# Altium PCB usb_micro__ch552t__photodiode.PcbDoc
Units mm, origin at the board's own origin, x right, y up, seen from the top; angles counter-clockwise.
Board outline 56 x 30 mm, 2 copper layers (Top, Bottom), stack 0 mm thick; 22 components, 15 nets, 85 pads, 32 vias.
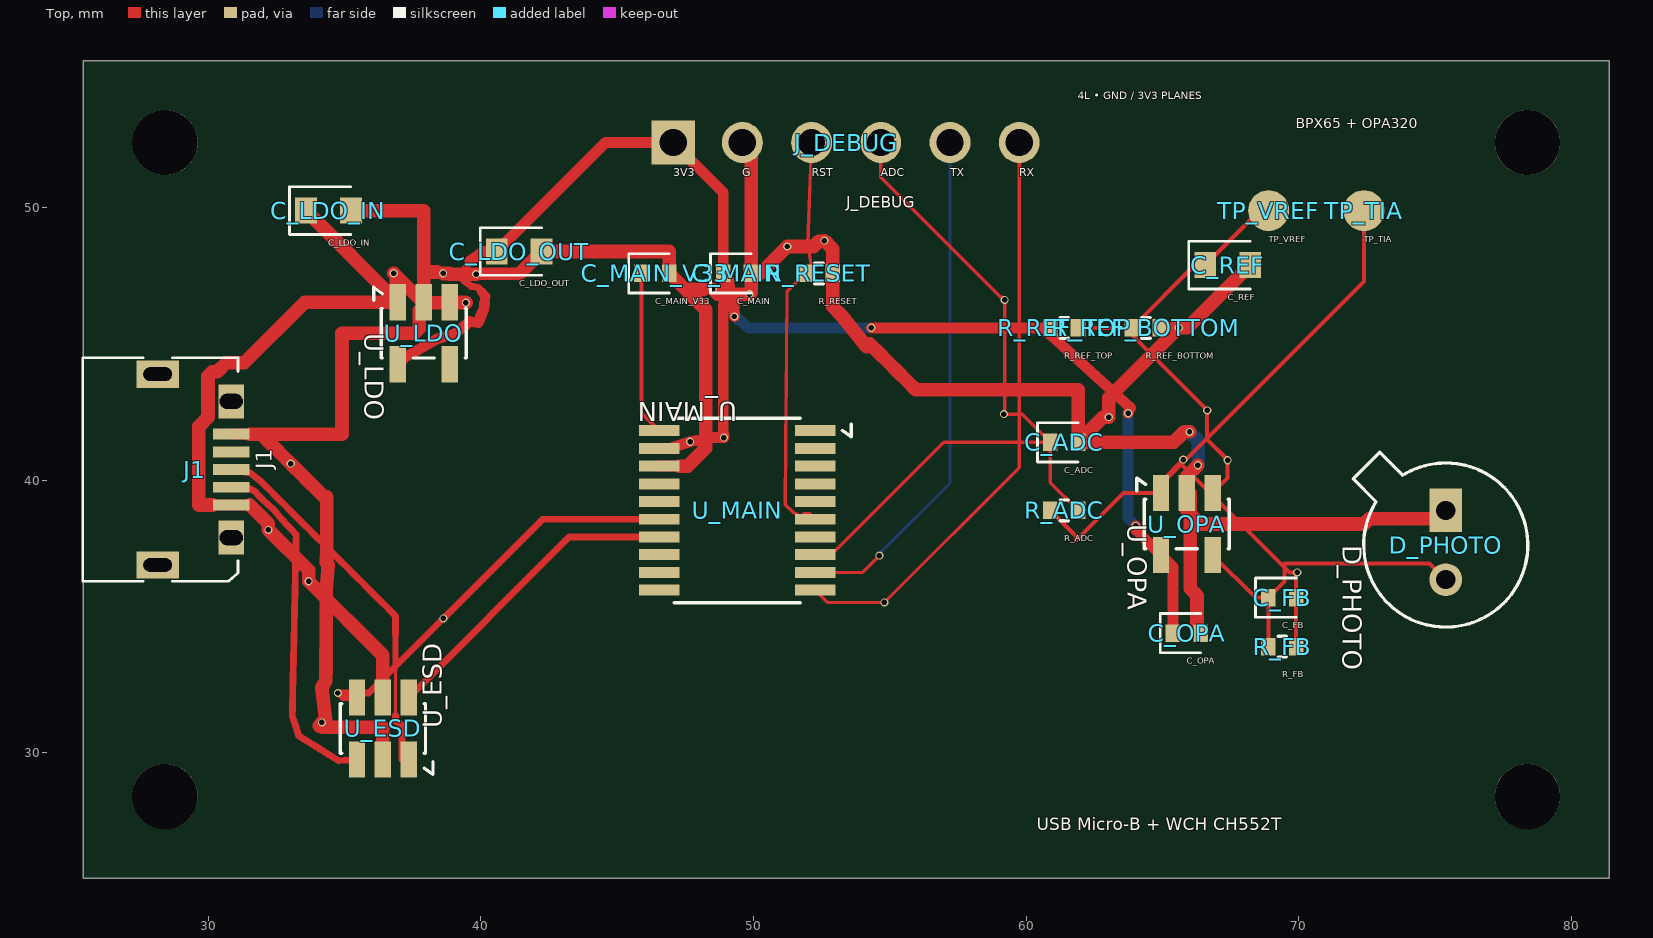
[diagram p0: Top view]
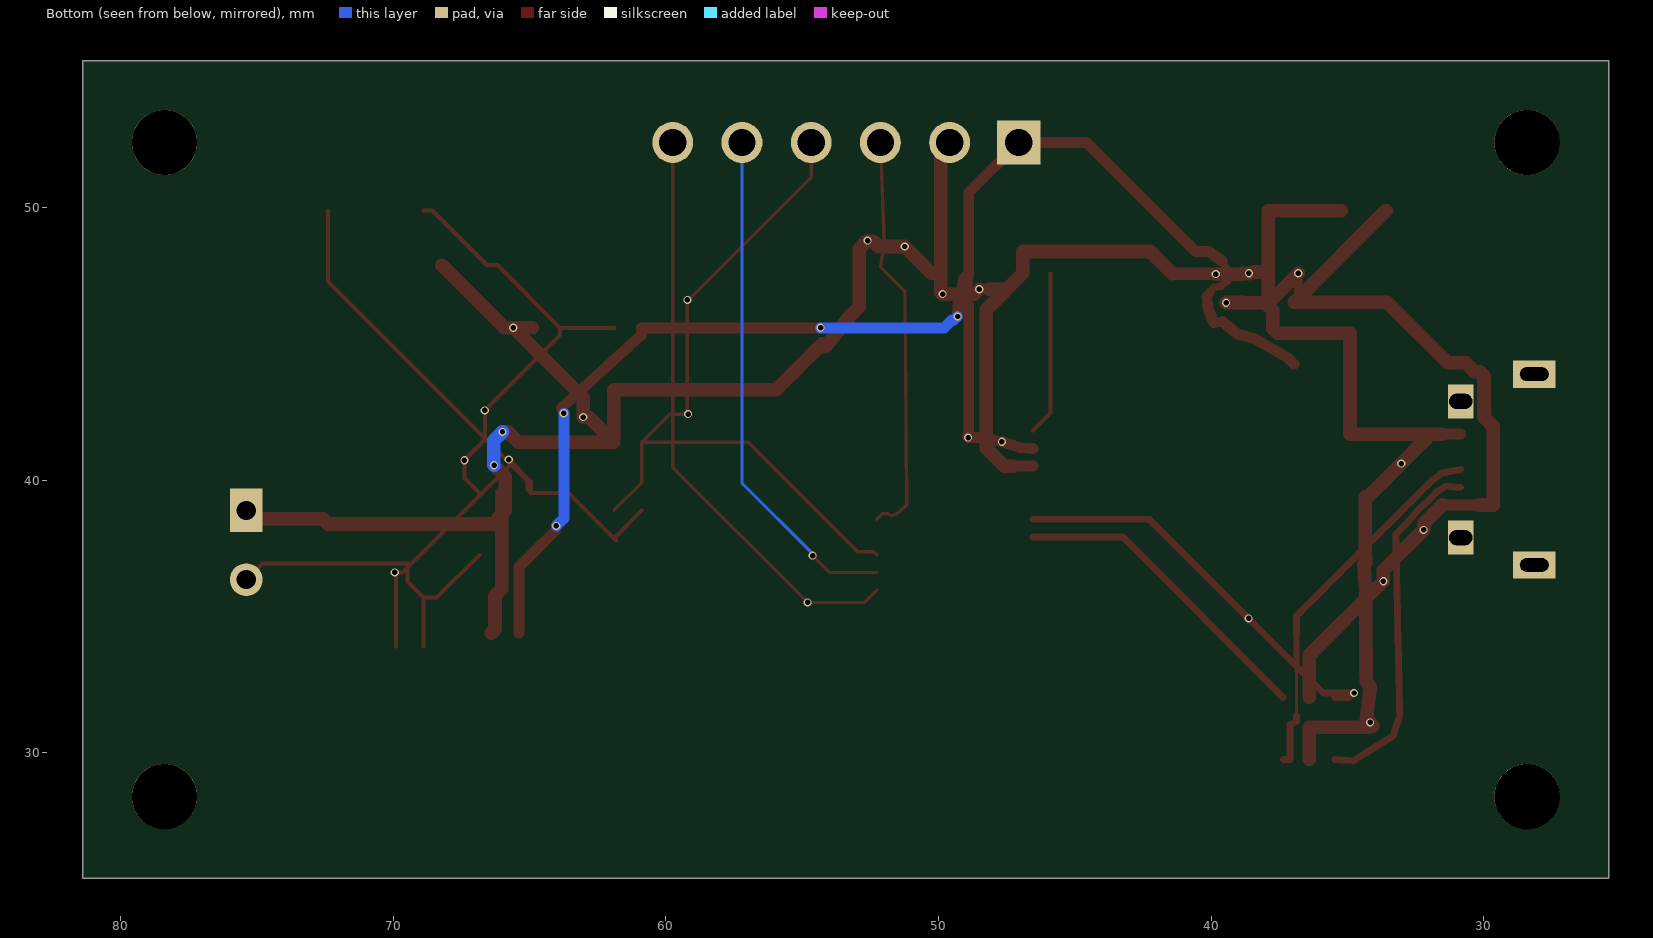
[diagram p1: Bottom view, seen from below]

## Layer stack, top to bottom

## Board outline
25.4,55.4 81.4,55.4 81.4,25.4 25.4,25.4

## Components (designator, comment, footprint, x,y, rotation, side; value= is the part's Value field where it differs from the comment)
C_ADC "" TSCIRCUIT-1.5600x0.6400mm 61.4,41.4 r0 top
C_FB "" TSCIRCUIT-1.5600x0.6400mm 69.4,35.7 r0 top
C_LDO_IN "" TSCIRCUIT-2.4500x0.9500mm 34.4,49.9 r0 top
C_LDO_OUT "" TSCIRCUIT-2.4500x0.9500mm 41.4,48.4 r0 top
C_MAIN "" TSCIRCUIT-1.5600x0.6400mm 49.4,47.6 r0 top
C_MAIN_V33 "" TSCIRCUIT-1.5600x0.6400mm 46.4,47.6 r0 top
C_OPA "" TSCIRCUIT-1.5600x0.6400mm 65.9,34.4 r0 top
C_REF "" TSCIRCUIT-2.4500x0.9500mm 67.4,47.9 r0 top
D_PHOTO "" TSCIRCUIT-1.2000x3.9400mm 75.4,37.73 r270 top
J1 "" TSCIRCUIT-4.1500x8mm 29.437,40.4 r90 top
J_DEBUG "" TSCIRCUIT-14.2000x1.5000mm 53.4,52.4 r0 top
R_ADC "" TSCIRCUIT-1.5600x0.6400mm 61.4,38.9 r0 top
R_FB "" TSCIRCUIT-1.5600x0.6400mm 69.4,33.9 r0 top
R_REF_BOTTOM "" TSCIRCUIT-1.5600x0.6400mm 64.4,45.6 r0 top
R_REF_TOP "" TSCIRCUIT-1.5600x0.6400mm 61.4,45.6 r0 top
R_RESET "" TSCIRCUIT-1.5600x0.6400mm 52.4,47.6 r0 top
TP_TIA "" TSCIRCUIT-1.5000x1.5000mm 72.4,49.9 r0 top
TP_VREF "" TSCIRCUIT-1.5000x1.5000mm 68.9,49.9 r0 top
U_ESD "" TSCIRCUIT-2.5000x3.6000mm#1 36.4,30.9 r90 top
U_LDO "" TSCIRCUIT-2.5000x3.6000mm#2 37.9,45.4 r270 top
U_MAIN "" TSCIRCUIT-7.2000x6.2500mm 49.4,38.9 r180 top
U_OPA "" TSCIRCUIT-2.5000x3.6000mm#2 65.9,38.4 r270 top

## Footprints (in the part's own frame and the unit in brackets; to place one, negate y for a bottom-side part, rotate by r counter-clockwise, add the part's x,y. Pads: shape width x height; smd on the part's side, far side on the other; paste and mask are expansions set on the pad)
TSCIRCUIT-1.2000x3.9400mm [mm]
  rect 1.6x1.2 hole 0.7: 1(-1.17,0)
  round 1.2 hole 0.7: 2(1.37,0)
  silkscreen extent -3.3,-3.4 3.11,3.01
TSCIRCUIT-1.5000x1.5000mm [mm]
  round 1.5 smd: 1(0,0)
TSCIRCUIT-1.5600x0.6400mm [mm]
  rect 0.54x0.64 smd: 1(-0.51,0) 2(0.51,0)
  silkscreen extent -0.98,-0.72 0.51,0.72
TSCIRCUIT-2.4500x0.9500mm [mm]
  rect 0.8x0.95 smd: 1(-0.825,0) 2(0.825,0)
  silkscreen extent -1.43,-0.87 0.82,0.87
TSCIRCUIT-2.5000x3.6000mm#1 [mm]
  rect 1.325x0.6 smd: 1(-1.137,-0.95) 2(-1.137,0) 3(-1.137,0.95) 4(1.138,0.95) 5(1.138,0) 6(1.138,-0.95)
  silkscreen extent -1.69,-1.84 0.91,1.56
TSCIRCUIT-2.5000x3.6000mm#2 [mm]
  rect 1.325x0.6 smd: 1(-1.137,-0.95) 2(-1.137,0) 3(-1.137,0.95) 4(1.138,0.95) 5(1.138,-0.95)
  silkscreen extent -1.69,-1.84 0.91,1.56
TSCIRCUIT-4.1500x8mm [mm]
  rect 0.4x1.35 smd: 1(-1.301,-1.4) 2(-0.65,-1.4) 3(0,-1.4) 4(0.65,-1.4) 5(1.3,-1.4)
  rect 1.25x0.95 hole 0.55 slot 0.85 at 90 deg: 6(2.5,-1.4) 7(-2.5,-1.4)
  rect 1x1.55 hole 0.5 slot 1.05 at 90 deg: 8(-3.5,1.3) 9(3.5,1.3)
  silkscreen extent -4.1,-1.65 4.1,4.05
TSCIRCUIT-7.2000x6.2500mm [mm]
  rect 1.475x0.4 smd: 1(-2.862,-2.925) 2(-2.862,-2.275) 3(-2.862,-1.625) 4(-2.862,-0.975) 5(-2.862,-0.325) 6(-2.862,0.325) 7(-2.862,0.975) 8(-2.862,1.625) 9(-2.862,2.275) 10(-2.862,2.925) 11(2.863,2.925) 12(2.863,2.275) 13(2.863,1.625) 14(2.863,0.975) 15(2.863,0.325) 16(2.863,-0.325) 17(2.863,-0.975) 18(2.863,-1.625) 19(2.863,-2.275) 20(2.863,-2.925)
  silkscreen extent -4.19,-3.38 2.31,3.39
TSCIRCUIT-14.2000x1.5000mm [mm]
  rect 1.6x1.6 hole 1: 1(-6.35,0)
  round 1.5 hole 1: 2(-3.81,0) 3(-1.27,0) 4(1.27,0) 5(3.81,0) 6(6.35,0)

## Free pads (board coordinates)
  round 2.4 hole 2.4 unplated: NPTH-1(28.4,28.4) NPTH-2(78.4,52.4) NPTH-3(78.4,28.4) NPTH-4(28.4,52.4)

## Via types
v1: diameter 0.3, hole 0.2, Top to Bottom, 32 vias

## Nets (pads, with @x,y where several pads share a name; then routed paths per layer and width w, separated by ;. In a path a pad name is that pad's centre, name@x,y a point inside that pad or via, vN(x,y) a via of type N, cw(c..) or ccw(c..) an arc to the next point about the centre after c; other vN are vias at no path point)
ADC_IN: C_ADC.1 J_DEBUG.4 R_ADC.2 U_MAIN.8 | length 27.3
  Top w0.12: U_MAIN.8 52.369,37.382 52.968,37.382 56.986,41.4 C_ADC.1 ; J_DEBUG.4 54.67,51.128 59.08,46.718 59.119,46.718 v1(59.214,46.623) 59.214,42.601 59.137,42.524 59.137,42.481 v1(59.186,42.432) 59.858,42.432 C_ADC.1 ; R_ADC.2 60.89,39.92 C_ADC.1
GND: C_ADC.2 C_LDO_IN.2 C_LDO_OUT.2 C_MAIN.2 C_MAIN_V33.2 C_OPA.2 C_REF.2 D_PHOTO.1 J1.5 J_DEBUG.2 R_REF_BOTTOM.2 R_RESET.2 U_ESD.2 U_LDO.2 U_MAIN.18 U_OPA.2 | length 115.4
  Top w0.312: 48.168,47.018 v1(48.506,47.018)
  Top w0.4: U_MAIN.18 U_MAIN.18@47.275,40.525 ; J1.5 31.513,41.7 31.203,41.7 J1.5
  Top w0.45: v1(39.828,47.571) 40.062,47.588 40.512,47.588 40.962,47.588 41.413,47.588
  Top w0.5: C_LDO_IN.2 37.9,49.9 U_LDO.2 ; U_ESD.2 36.4,30.942 34.193,30.942 34.147,30.989 34.063,30.989 v1(34.161,31.121) 34.302,31.196 34.15,32.4 34.31,32.643 34.312,33.125 34.315,33.607 34.317,34.089 34.32,34.571 34.322,35.053 34.325,35.535 34.327,36.018 34.4,36.9 34.332,36.982 34.335,37.464 34.338,37.946 34.34,38.428 34.343,38.91 34.345,39.393 34.236,39.398 33.952,39.682 33.668,39.966 33.384,40.25 33.1,40.534 v1(33.016,40.618) 32.745,40.889 32.475,41.159 32.204,41.43 31.934,41.7 31.569,41.7 31.513,41.7 34.9,41.7 34.9,45.4 37.567,45.4 37.733,45.567 37.733,46.233 37.9,46.4 U_LDO.2 ; v1(39.828,47.571) 39.344,47.571 38.861,47.571 38.838,47.594 38.619,47.594 v1(38.608,47.605) 38.4,47.65 37.9,47.65 U_LDO.2 ; 41.413,47.588 41.684,47.859 41.954,48.129 C_LDO_OUT.2 46.91,48.4 C_MAIN_V33.2 ; 47.275,40.525 47.588,40.525 48.242,41.179 48.242,46.268 C_MAIN_V33.2 ; 48.168,47.018 47.83,47.018 47.492,47.018 C_MAIN_V33.2 ; v1(48.506,47.018) 48.689,46.835 v1(49.851,46.835) 49.91,46.894 C_MAIN.2 ; J_DEBUG.2 49.91,52.08 C_MAIN.2 ; v1(65.997,41.782) 65.988,41.791 65.808,41.791 65.612,41.595 65.417,41.4 64.978,41.4 64.54,41.4 64.102,41.4 63.663,41.4 63.225,41.4 62.787,41.4 62.348,41.4 C_ADC.2 ; v1(66.307,40.557) 65.9,40.15 U_OPA.2 ; C_OPA.2 66.4,34.4 66.275,34.525 66.275,35.775 66.025,36.025 66.025,39.525 65.912,39.525 U_OPA.2 ; C_REF.2 65.925,45.6 R_REF_BOTTOM.2 65.41,45.6 v1(65.6,45.6) 63.036,43.036 v1(63.036,42.324) 62.834,42.324 C_ADC.2 ; D_PHOTO.1 75.089,38.589 74.611,38.589 74.134,38.589 73.657,38.589 73.18,38.589 72.703,38.589 72.589,38.589 72.4,38.4 66.15,38.4 66.15,38.65 65.9,38.9 U_OPA.2 ; C_MAIN.2 50.255,47.6 51.232,48.577 v1(51.238,48.583) 52.206,48.583 52.405,48.782 52.582,48.782 v1(52.6,48.8) 52.91,48.49 R_RESET.2 52.91,47.19 52.91,46.78 52.91,46.37 53.249,46.032 54.15,44.9 54.265,45.015 54.604,44.677 54.942,44.338 55.281,43.999 55.62,43.66 55.959,43.322 61.91,43.322 C_ADC.2
  Bottom w0.5: v1(65.997,41.782) 66.317,41.462 66.317,41.064 66.317,40.666 66.317,40.567 v1(66.307,40.557)
MAIN_RESET: J_DEBUG.3 R_RESET.1 U_MAIN.6 | length 15
  Top w0.12: J_DEBUG.3 51.987,48.657 52.13,47.84 R_RESET.1 51.231,46.941 51.164,39.1 51.458,38.828 51.741,38.703 51.847,38.776 52.062,38.776 U_MAIN.6
MAIN_V33: C_MAIN_V33.1 U_MAIN.20 | length 6
  Top w0.15: C_MAIN_V33.1 45.89,42.472 U_MAIN.20
PD_SUM: C_FB.1 D_PHOTO.2 R_FB.1 U_OPA.4 | length 12.2
  Top w0.15: U_OPA.4 68.412,35.7 C_FB.1 ; R_FB.1 C_FB.1 ; D_PHOTO.2 74.804,36.956 69.479,36.956 69.479,36.289 C_FB.1
TIA_OUT: C_FB.2 R_ADC.1 R_FB.2 TP_TIA.1 U_OPA.1 | length 29.2
  Top w0.15: R_ADC.1 61.839,37.951 61.839,37.8 63.577,39.538 U_OPA.1 ; R_FB.2 C_FB.2 69.91,36.45 69.91,36.584 v1(69.95,36.624) 69.661,36.624 65.642,40.643 v1(65.766,40.767) 64.95,39.951 U_OPA.1 ; TP_TIA.1 72.4,47.296 65.085,39.981 65.085,39.672 U_OPA.1
UART_MAIN_RX: J_DEBUG.6 U_MAIN.10 | length 21.7
  Top w0.12: U_MAIN.10 52.713,35.525 v1(54.804,35.525) 54.819,35.54 59.75,40.471 J_DEBUG.6
UART_MAIN_TX: J_DEBUG.5 U_MAIN.9 | length 18.8
  Top w0.12: U_MAIN.9 54.002,36.625 v1(54.62,37.243)
  Bottom w0.12: v1(54.62,37.243) 54.665,37.288 54.665,37.359 57.21,39.904 J_DEBUG.5
USB_DM_MCU: U_ESD.4 U_MAIN.15 | length 15.2
  Top w0.25: U_ESD.4 34.93,32.038 34.768,32.2 v1(34.75,32.2) 35.881,32.2 38.615,34.934 v1(38.62,34.939) 42.256,38.575 46.289,38.575 U_MAIN.15
USB_DM_PORT: J1.2 U_ESD.3 | length 12.9
  Top w0.25: J1.2 31.017,39.762 31.196,39.775 31.374,39.787 31.542,39.688 31.71,39.588 31.877,39.414 32.045,39.24 32.412,38.909 32.717,38.543 32.884,38.369 33.052,38.194 33.22,38.02 33.215,37.774 33.209,37.527 33.204,37.281 33.198,37.035 33.193,36.788 33.188,36.542 33.182,36.295 33.177,36.049 33.171,35.802 33.166,35.556 33.161,35.309 33.155,35.063 33.15,34.817 33.144,34.57 33.139,34.324 33.133,34.077 33.128,33.831 33.123,33.584 33.117,33.338 33.112,33.092 33.106,32.845 33.101,32.599 33.096,32.352 33.09,32.106 33.085,31.859 33.079,31.613 33.074,31.366 33.135,31.18 33.195,30.994 33.256,30.808 33.316,30.621 33.524,30.492 33.732,30.363 33.94,30.234 34.148,30.104 34.355,29.975 34.563,29.846 34.771,29.716 34.997,29.732 35.224,29.747 U_ESD.3
USB_DP_MCU: U_ESD.6 U_MAIN.14 | length 11.6
  Top w0.25: U_ESD.6 43.238,37.925 U_MAIN.14
USB_DP_PORT: J1.3 U_ESD.1 | length 13.9
  Top w0.12: 36.86,31.383 36.86,31.615 36.86,31.846 36.86,32.078 36.86,32.309 36.86,32.541 36.86,32.772 36.86,32.998
  Top w0.15: 36.86,32.998 36.86,33.224
  Top w0.219: 36.86,33.224 36.86,33.45 36.86,33.675 36.86,33.901 36.86,34.127
  Top w0.225: 36.86,34.127 36.86,34.353
  Top w0.25: J1.3 31.525,40.275 31.916,39.974 32.092,39.798 32.269,39.621 32.445,39.445 32.622,39.268 32.799,39.091 32.975,38.915 33.152,38.738 33.328,38.562 33.505,38.385 33.681,38.209 33.858,38.032 34.035,37.855 34.211,37.679 34.388,37.502 34.564,37.326 34.741,37.149 34.918,36.972 35.094,36.796 35.271,36.619 35.447,36.443 35.624,36.266 35.8,36.09 35.977,35.913 36.154,35.736 36.33,35.56 36.507,35.383 36.683,35.207 36.86,35.03 36.86,34.804 36.86,34.578 36.86,34.353 ; 36.86,31.383 36.86,31.152 37.1,31.032 37.1,30.821 37.1,30.609 37.1,30.397 37.1,30.186 37.1,29.974 37.1,29.763 U_ESD.1
VBUS5: C_LDO_IN.1 J1.1 U_ESD.5 U_LDO.1 U_LDO.3 | length 33.5
  Top w0.312: U_LDO.1@36.8,46.688 v1(36.8,47.6)
  Top w0.4: J1.1@30.163,39.099 J1.1 31.175,39.099 31.513,39.099
  Top w0.5: J1.1@30.163,39.099 29.65,39.099 29.65,41.983 29.983,42.317 29.983,43.817 30.15,43.983 30.317,43.983 30.65,44.317 31.317,44.317 33.537,46.537 33.58,46.537 34.062,46.537 34.543,46.537 35.024,46.537 35.506,46.537 35.987,46.537 36.469,46.537 U_LDO.1 ; 31.513,39.099 32.198,38.414 v1(32.198,38.184) 33.676,36.707 v1(33.676,36.302) 36.4,33.578 U_ESD.5 ; C_LDO_IN.1 36.938,46.537 U_LDO.1 ; U_LDO.1@36.8,46.688 U_LDO.1 ; v1(36.8,47.6) 37.883,46.517 v1(39.448,46.517) 39.428,46.537 U_LDO.3
VCC_3V3: C_LDO_OUT.1 C_MAIN.1 C_OPA.1 J_DEBUG.1 R_REF_TOP.1 U_LDO.5 U_MAIN.19 U_OPA.5 | length 56.2
  Top w0.26: 39.373,47.325 39.366,47.699 39.482,47.873
  Top w0.262: 39.373,47.325 39.635,47.133 ; 39.482,47.873 39.599,48.048
  Top w0.275: 39.635,47.133 39.897,47.079 40.028,46.914
  Top w0.337: 40.028,46.914 40.159,46.748
  Top w0.363: 40.13,46.505 40.159,46.748
  Top w0.387: 40.1,46.263 40.13,46.505
  Top w0.4: U_LDO.5 37.184,44.497 38.4,45.2 39.05,45.387 39.312,45.606 39.575,45.825 39.9,45.8 40.1,46.263 ; 39.599,48.048 39.833,48.224 40.067,48.4 40.321,48.4 C_LDO_OUT.1 44.575,52.4 J_DEBUG.1 48.89,50.56 C_MAIN.1 ; U_MAIN.19 47,41.2 v1(47.673,41.42) 47.909,41.463 48.069,41.463 48.174,41.567 48.544,41.569 v1(48.915,41.572) 48.873,41.665 48.915,41.665 48.89,41.69 48.89,42.084 48.89,42.478 48.89,42.872 48.89,43.266 48.89,43.66 48.89,44.054 48.89,44.448 48.89,44.842 48.89,45.236 48.89,45.63 48.89,46.024 48.89,46.418 49,46.8 C_MAIN.1 ; v1(49.298,46.015) 49.289,46.401 49.159,46.779 49.081,47.387 C_MAIN.1 ; v1(54.325,45.6) 54.39,45.6 54.772,45.6 55.155,45.6 55.537,45.6 55.919,45.6 56.302,45.6 56.684,45.6 57.066,45.6 57.449,45.6 57.831,45.6 58.214,45.6 58.596,45.6 58.978,45.6 59.361,45.6 59.743,45.6 60.125,45.6 60.508,45.6 R_REF_TOP.1 60.903,45.338 63.838,42.655 v1(63.748,42.467) ; v1(64.024,38.33) 64.024,38.188 U_OPA.5 65.39,36.822 C_OPA.1
  Bottom w0.4: v1(49.298,46.015) 49.439,45.892 49.499,45.892 49.645,45.746 49.791,45.6 50.169,45.6 50.546,45.6 50.924,45.6 51.302,45.6 51.68,45.6 52.058,45.6 52.436,45.6 52.814,45.6 53.191,45.6 53.569,45.6 53.947,45.6 v1(54.325,45.6) ; v1(63.748,42.467) 63.748,38.606 63.992,38.362 v1(64.024,38.33)
VREF_0V5: C_REF.1 R_REF_BOTTOM.1 R_REF_TOP.2 TP_VREF.1 U_OPA.3 | length 16.5
  Top w0.15: R_REF_TOP.2 R_REF_BOTTOM.1 ; U_OPA.3 67.395,40.082 v1(67.395,40.742) 67.31,40.827 67.31,40.845 66.647,41.507 v1(66.647,42.569) 66.527,42.689 66.527,42.695 63.89,45.332 R_REF_BOTTOM.1 ; TP_VREF.1 68.575,49.9 C_REF.1 66.19,47.9 R_REF_BOTTOM.1
pads on no net: J1.4 J1.6 J1.7 J1.8 J1.9 U_LDO.4 U_MAIN.1 U_MAIN.2 U_MAIN.3 U_MAIN.4 U_MAIN.5 U_MAIN.7 U_MAIN.11 U_MAIN.12 U_MAIN.13 U_MAIN.16 U_MAIN.17

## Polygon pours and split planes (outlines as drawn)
GND on Mid1 (solid): 81.1,55.1 25.7,55.1 25.7,25.7 81.1,25.7
GND on Mid1 (solid): 59.49,46.335 59.474,46.321 59.474,42.709 59.49,42.689
VCC_3V3 on Mid2 (solid): 81.1,55.1 25.7,55.1 25.7,25.7 81.1,25.7

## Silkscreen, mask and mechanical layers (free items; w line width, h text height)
Top Overlay:
  text "4L • GND / 3V3 PLANES" at 61.9,53.9 h0.48
  text "BPX65 + OPA320" at 69.9,52.8 h0.65
  text "USB Micro-B + WCH CH552T" at 60.4,27 h0.78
